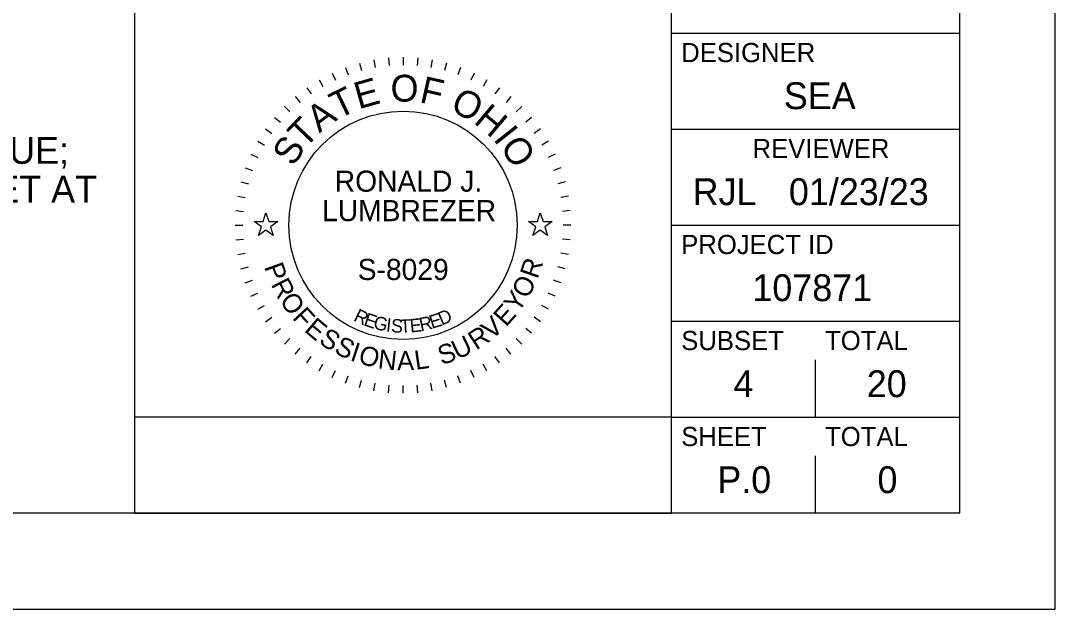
# Model space of a CAD drawing. Extents: x -10.5 to 54.7, y 0 to 22.
# Drawn here: x 28.61 to 34, y 0 to 3.07 of the extents above; entities that cross this region are included whole.
import ezdxf

# ---------------------------------------------------------------- set-up
doc = ezdxf.new("R2010")
doc.units = 0
for name, color, linetype in [('Default', 7, 'Continuous'), ('SH_Border', 7, 'Continuous'), ('SH_Cut_Line', 7, 'Continuous'), ('SH_Data', 7, 'Continuous'), ('SH_Text', 7, 'Continuous')]:
    doc.layers.add(name, color=color, linetype=linetype)

msp = doc.modelspace()

# ---------------------------------------------------------------- linework, layer by layer
at = {"layer": 'Default'}
for points in [[(29.8236, 2.02), (29.8705, 2.02), (29.885, 2.0645), (29.8995, 2.02), (29.9464, 2.02), (29.9085, 1.9924), (29.923, 1.9478), (29.885, 1.9754), (29.847, 1.9478), (29.8615, 1.9924)], [(31.2536, 2.02), (31.3005, 2.02), (31.315, 2.0645), (31.3295, 2.02), (31.3764, 2.02), (31.3385, 1.9924), (31.353, 1.9478), (31.315, 1.9754), (31.277, 1.9478), (31.2915, 1.9924)]]:
    msp.add_lwpolyline(points, close=True, dxfattribs=at)
at = {"layer": 'SH_Border'}
for p, q in [((32, 0.5), (32, 21.5)), ((32, 3), (33.5, 3)), ((32, 2.5), (33.5, 2.5)), ((32, 2), (33.5, 2)), ((32, 1.5), (33.5, 1.5)), ((32, 1), (33.5, 1))]:
    msp.add_line(p, q, dxfattribs=at)
msp.add_lwpolyline([(1.5, 21.5), (33.5, 21.5), (33.5, 0.5), (1.5, 0.5)], close=True, dxfattribs=at)
at = {"layer": 'SH_Cut_Line'}
msp.add_lwpolyline([(0, 0), (34, 0), (34, 22), (0, 22)], close=True, dxfattribs=at)
at = {"layer": 'SH_Data'}
for p, q in [((29.2, 3.75), (29.2, 0.5)), ((32, 0.5), (32, 3.75)), ((30.4481, 2.8617), (30.455, 2.8223)), ((30.5237, 2.8717), (30.5272, 2.8318)), ((30.6, 2.875), (30.6, 2.835)), ((30.6763, 2.8717), (30.6728, 2.8318)), ((30.7519, 2.8617), (30.745, 2.8223)), ((30.3007, 2.8222), (30.3144, 2.7846)), ((30.3735, 2.8452), (30.3839, 2.8065)), ((30.8265, 2.8452), (30.8161, 2.8065)), ((30.8993, 2.8222), (30.8856, 2.7846)), ((30.1625, 2.7578), (30.1825, 2.7231)), ((30.2302, 2.793), (30.2471, 2.7568)), ((30.9698, 2.793), (30.9529, 2.7568)), ((31.0375, 2.7578), (31.0175, 2.7231)), ((30.0981, 2.7168), (30.1211, 2.684)), ((31.1019, 2.7168), (31.0789, 2.684)), ((30.0376, 2.6703), (30.0633, 2.6396)), ((31.1624, 2.6703), (31.1367, 2.6396)), ((29.9813, 2.6187), (30.0096, 2.5904)), ((31.2187, 2.6187), (31.1904, 2.5904)), ((29.9297, 2.5624), (29.9604, 2.5367)), ((31.2703, 2.5624), (31.2396, 2.5367)), ((29.8832, 2.5019), (29.916, 2.4789)), ((31.3168, 2.5019), (31.284, 2.4789)), ((29.8422, 2.4375), (29.8769, 2.4175)), ((31.3578, 2.4375), (31.3231, 2.4175)), ((29.807, 2.3698), (29.8432, 2.3529)), ((31.393, 2.3698), (31.3568, 2.3529)), ((29.7778, 2.2993), (29.8154, 2.2856)), ((31.4222, 2.2993), (31.3846, 2.2856)), ((29.7548, 2.2265), (29.7935, 2.2161)), ((31.4452, 2.2265), (31.4065, 2.2161)), ((29.7383, 2.1519), (29.7777, 2.145)), ((31.4617, 2.1519), (31.4223, 2.145)), ((29.7283, 2.0763), (29.7682, 2.0728)), ((31.4717, 2.0763), (31.4318, 2.0728)), ((29.725, 2), (29.765, 2)), ((31.475, 2), (31.435, 2)), ((29.7283, 1.9237), (29.7682, 1.9272)), ((31.4717, 1.9237), (31.4318, 1.9272)), ((29.7383, 1.8481), (29.7777, 1.855)), ((31.4617, 1.8481), (31.4223, 1.855)), ((29.7548, 1.7735), (29.7935, 1.7839)), ((31.4452, 1.7735), (31.4065, 1.7839)), ((29.7778, 1.7007), (29.8154, 1.7144)), ((31.4222, 1.7007), (31.3846, 1.7144)), ((29.807, 1.6302), (29.8432, 1.6471)), ((31.393, 1.6302), (31.3568, 1.6471)), ((29.8422, 1.5625), (29.8769, 1.5825)), ((31.3578, 1.5625), (31.3231, 1.5825)), ((29.8832, 1.4981), (29.916, 1.5211)), ((31.3168, 1.4981), (31.284, 1.5211)), ((29.9297, 1.4376), (29.9604, 1.4633)), ((31.2703, 1.4376), (31.2396, 1.4633)), ((29.9813, 1.3813), (30.0096, 1.4096)), ((31.2187, 1.3813), (31.1904, 1.4096)), ((30.0376, 1.3297), (30.0633, 1.3604)), ((31.1624, 1.3297), (31.1367, 1.3604)), ((30.0981, 1.2832), (30.1211, 1.316)), ((31.1019, 1.2832), (31.0789, 1.316)), ((32.75, 1), (32.75, 1.3)), ((30.1625, 1.2422), (30.1825, 1.2769)), ((30.2302, 1.207), (30.2471, 1.2432)), ((30.9698, 1.207), (30.9529, 1.2432)), ((31.0375, 1.2422), (31.0175, 1.2769)), ((30.3007, 1.1778), (30.3144, 1.2154)), ((30.3735, 1.1548), (30.3839, 1.1935)), ((30.8265, 1.1548), (30.8161, 1.1935)), ((30.8993, 1.1778), (30.8856, 1.2154)), ((30.4481, 1.1383), (30.455, 1.1777)), ((30.5237, 1.1283), (30.5272, 1.1682)), ((30.6, 1.125), (30.6, 1.165)), ((30.6763, 1.1283), (30.6728, 1.1682)), ((30.7519, 1.1383), (30.745, 1.1777)), ((32.75, 0.5), (32.75, 0.8)), ((32.375, 0.675), (32.375, 0.675)), ((32, 0.5), (29.2, 0.5))]:
    msp.add_line(p, q, dxfattribs=at)
msp.add_lwpolyline([(32, 0.5), (32, 1), (29.2, 1), (29.2, 0.5)], close=True, dxfattribs=at)
msp.add_circle((30.6, 2), 0.595, dxfattribs=at)

# ---------------------------------------------------------------- texts
for s, height, p in [('DESIGNER', 0.1, (32.05, 2.85)), ('SEA', 0.14, (32.5848, 2.605)), ('REVIEWER', 0.1, (32.4218, 2.35)), ('RONALD J.', 0.11, (30.2441, 2.1749)), ('RJL', 0.14, (32.1095, 2.105)), ('01/23/23', 0.14, (32.6113, 2.105)), ('LUMBREZER', 0.11, (30.1779, 2.0216)), ('PROJECT ID', 0.1, (32.05, 1.85)), ('S-8029', 0.11, (30.3636, 1.7151)), ('107871', 0.14, (32.4208, 1.605)), ('SUBSET', 0.1, (32.05, 1.35)), ('TOTAL', 0.1, (32.8, 1.35)), ('4', 0.14, (32.3223, 1.105)), ('20', 0.14, (33.0171, 1.105)), ('SHEET', 0.1, (32.05, 0.85)), ('TOTAL', 0.1, (32.8, 0.85)), ('P.0', 0.14, (32.2381, 0.605)), ('0', 0.14, (33.0729, 0.605))]:
    msp.add_text(s, height=height, dxfattribs=at).set_placement(p)
for s, height, rotation, p in [('E', 0.14, 15.7571, (30.3684, 2.6038)), ('O', 0.14, 359.7812, (30.5347, 2.6443)), ('F', 0.14, 347.4362, (30.6811, 2.6417)), ('T', 0.14, 25.7167, (30.2616, 2.5518)), ('O', 0.14, 332.2586, (30.8398, 2.6015)), ('A', 0.14, 36.4747, (30.1634, 2.4781)), ('H', 0.14, 319.9136, (30.9632, 2.5361)), ('T', 0.14, 46.4344, (30.0883, 2.3964)), ('I', 0.14, 308.367, (31.0665, 2.4483)), ('S', 0.14, 57.1924, (30.0281, 2.3014)), ('O', 0.14, 303.1491, (31.1021, 2.4089)), ('P', 0.1, 289.7431, (29.8753, 1.7841)), ('R', 0.1, 70.983, (31.3009, 1.7167)), ('R', 0.1, 296.9802, (29.9093, 1.6927)), ('O', 0.1, 62.7428, (31.2501, 1.6133)), ('O', 0.1, 304.7158, (29.9532, 1.6079)), ('Y', 0.1, 55.5058, (31.2, 1.54)), ('F', 0.1, 312.956, (30.0192, 1.5158)), ('R', 0.07, 334.487, (30.3375, 1.5051)), ('E', 0.1, 48.2687, (31.1366, 1.4673)), ('E', 0.1, 319.6885, (30.0808, 1.4504)), ('E', 0.07, 341.04, (30.3906, 1.4801)), ('G', 0.07, 347.4752, (30.4414, 1.4618)), ('I', 0.07, 353.7858, (30.5091, 1.4468)), ('S', 0.07, 356.8926, (30.5358, 1.4429)), ('T', 0.07, 3.0061, (30.5857, 1.4387)), ('E', 0.07, 6.0117, (30.6389, 1.4412)), ('R', 0.07, 11.9184, (30.6925, 1.4474)), ('E', 0.07, 17.6836, (30.7498, 1.4602)), ('D', 0.07, 23.3052, (30.801, 1.477)), ('V', 0.1, 41.0316, (31.0615, 1.4007)), ('S', 0.1, 326.9255, (30.1554, 1.3885)), ('R', 0.1, 33.296, (30.9815, 1.3473)), ('S', 0.1, 334.1626, (30.236, 1.3374)), ('U', 0.1, 25.5604, (30.8833, 1.2986)), ('I', 0.1, 341.3997, (30.3191, 1.2979)), ('O', 0.1, 345.1351, (30.3618, 1.2821)), ('N', 0.1, 353.3752, (30.466, 1.2555)), ('L', 0.1, 8.3479, (30.6664, 1.2467)), ('S', 0.1, 18.3234, (30.8005, 1.2711)), ('A', 0.1, 1.1108, (30.5692, 1.2443))]:
    msp.add_text(s, height=height, rotation=rotation, dxfattribs=at).set_placement(p)
at = {"layer": 'SH_Text'}
for s, p in [('HAVE ESTABLISHED THE PROPOSED BOUNDARY LINES, CALCULATED THE GROSS TAKE, PRESENT ROADWAY OCCUPIED (PRO), NET TAKE AND NET RESIDUE;', (14.264, 2.3203)), ('AS WELL AS PREPARED THE LEGAL DESCRIPTIONS NECESSARY TO ACQUIRE THE PARCELS AS SHOWN HEREIN.  AS A PART OF THIS WORK, RIGHT OF WAY MONUMENTS WILL BE SET AT', (11.8512, 2.1178))]:
    msp.add_text(s, height=0.1399997, dxfattribs=at).set_placement(p)

doc.saveas('drawing.dxf')
